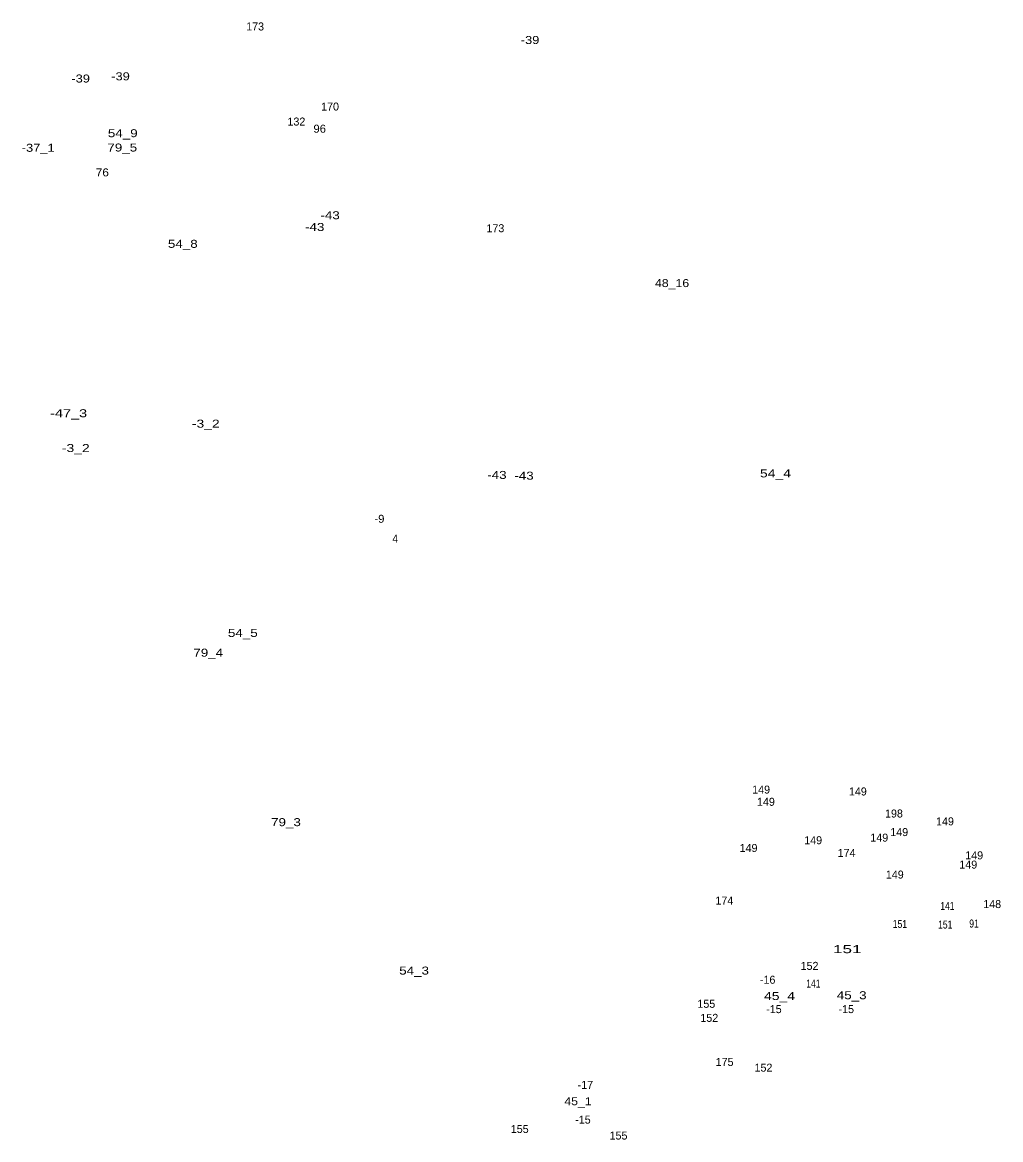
# Model space of a CAD drawing. Extents: x -660405 to -657848, y -988475 to -986360.
# Drawn here: x -658337 to -657848, y -987923 to -987365 of the extents above; entities that cross this region are included whole.
import ezdxf
from ezdxf.enums import TextEntityAlignment as Align

# ---------------------------------------------------------------- set-up
doc = ezdxf.new("R2010")
doc.units = 0
doc.header["$LTSCALE"] = 1.6
doc.layers.add('24', color=7, linetype='Continuous')

msp = doc.modelspace()

# ---------------------------------------------------------------- texts
at = {"layer": '24'}
for s, p in [('173', (-658220.801, -987369.21)), ('170', (-658183.341, -987409.22)), ('132', (-658200.16, -987416.71)), ('173', (-658100.74, -987470)), ('149', (-657967.98, -987750.46)), ('149', (-657919.65, -987751.38)), ('149', (-657965.58, -987756.55)), ('198', (-657901.611, -987762.4)), ('149', (-657876.11, -987766.33)), ('149', (-657941.97, -987775.74)), ('149', (-657908.95, -987774.45)), ('149', (-657898.99, -987771.68)), ('149', (-657974.26, -987779.62)), ('174', (-657925.28, -987782.1)), ('149', (-657861.53, -987783.31)), ('149', (-657901.2, -987792.91)), ('149', (-657864.49, -987787.92)), ('174', (-657986.33, -987805.87)), ('148', (-657852.53, -987807.64)), ('152', (-657943.78, -987838.52)), ('-16', (-657964.71, -987845.45)), ('155', (-657995.35, -987857.46)), ('152', (-657993.87, -987864.49)), ('-15', (-657961.581, -987860.12)), ('-15', (-657925.421, -987860.12)), ('175', (-657986.221, -987886.52)), ('152', (-657966.809, -987889.36)), ('-17', (-658055.77, -987897.97)), ('-15', (-658057, -987915.33)), ('155', (-658088.579, -987920)), ('155', (-658039.23, -987923.28))]:
    msp.add_text(s, height=4, dxfattribs=at).set_placement(p, align=Align.CENTER)
for s, width, p in [('-39', 1.2, (-658083.42, -987375.97)), ('-39', 1.2, (-658307.95, -987395.22)), ('-39', 1.2, (-658288.03, -987394.12)), ('54_9', 1.25, (-658286.91, -987422.53)), ('96', 1.05, (-658188.51, -987420.29)), ('-37_1', 1.2, (-658329.16, -987429.82)), ('79_5', 1.25, (-658287.16, -987429.68)), ('76', 1.1, (-658297.12, -987442.11)), ('-43', 1.25, (-658183.33, -987463.52)), ('-43', 1.25, (-658191.01, -987469.37)), ('54_8', 1.25, (-658256.91, -987477.8)), ('48_16', 1.15, (-658012.47, -987497.41)), ('-47_3', 1.35, (-658313.949, -987562.43)), ('-3_2', 1.3, (-658245.449, -987567.65)), ('-3_2', 1.3, (-658310.39, -987579.83)), ('-43', 1.25, (-658099.97, -987593.25)), ('-43', 1.25, (-658086.44, -987593.62)), ('54_4', 1.3, (-657960.811, -987592.49)), ('-9', 1.05, (-658158.67, -987615.16)), ('4', 0.95, (-658150.79, -987625.03)), ('54_5', 1.25, (-658226.921, -987672.19)), ('79_4', 1.25, (-658244.21, -987682.06)), ('79_3', 1.25, (-658205.37, -987766.72)), ('141', 0.8, (-657874.9, -987808.58)), ('151', 0.8, (-657898.63, -987817.59)), ('151', 0.8, (-657875.99, -987817.87)), ('91', 0.8, (-657861.601, -987817.36)), ('151', 1.6, (-657924.934, -987830.17)), ('54_3', 1.25, (-658141.351, -987840.87)), ('141', 0.8, (-657941.87, -987847.34)), ('45_4', 1.3, (-657958.791, -987853.59)), ('45_3', 1.25, (-657922.721, -987853.19)), ('45_1', 1.15, (-658059.459, -987906.16))]:
    msp.add_text(s, height=4, dxfattribs=dict(at, width=width)).set_placement(p, align=Align.CENTER)

doc.saveas('drawing.dxf')
